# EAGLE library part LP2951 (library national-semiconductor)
Adjustable Micropower Voltage Regulator Source: http://www.national.com/ds/LP/LP2950.pdf
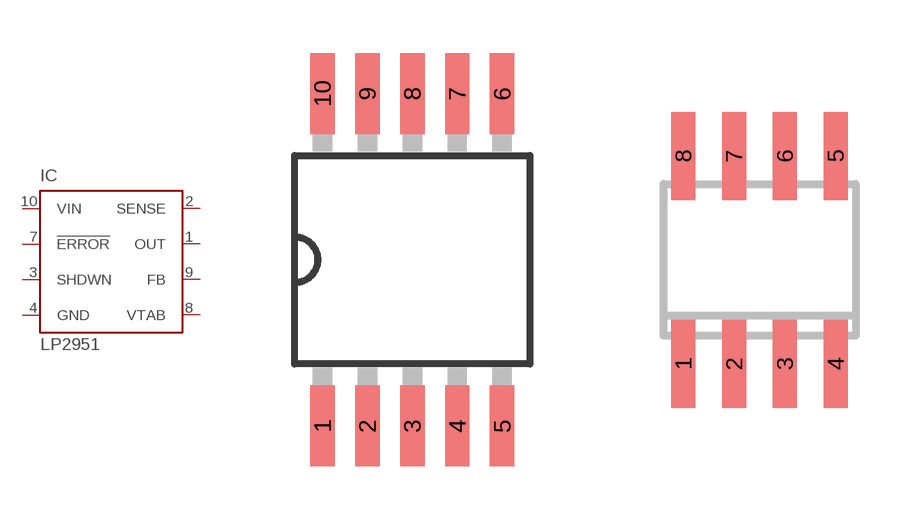
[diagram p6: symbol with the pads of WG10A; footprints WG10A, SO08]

Designator prefix IC

## LP2951WG (OC_FARNELL: unknown; OC_NEWARK: unknown)  [WG10A]
1  OUT  out
2  SENSE  in
3  SHDWN  in
4  GND  pwr
7  !ERROR  out
8  VTAB  in
9  FB  in
10  VIN  in

## LP2951M (MF: FAIRCHILD SEMICONDUCTOR; MPN: LP2951CM; OC_FARNELL: 9488561; OC_NEWARK: 78K6014)  [SO08]
1  OUT  out
2  SENSE  in
3  SHDWN  in
4  GND  pwr
5  !ERROR  out
6  VTAB  in
7  FB  in
8  VIN  in

## LP2951N (MF: ON SEMICONDUCTOR; MPN: LP2951CN; OC_FARNELL: 9489320; OC_NEWARK: 20C0799)  [DIL08]
Pads as for SO08

## LP2951H (OC_FARNELL: unknown; OC_NEWARK: unknown)  [H08C]
Pads as for SO08

## LP2951D (MPN: LP2951D; OC_FARNELL: 1389844; OC_NEWARK: 48M0679)  [LLP8]
Pads as for SO08

## Footprint WG10A (pad centres in mm)
NS Package Number WG10A Source: http://www.national.com/ds/LP/LP2950.pdf
smd 0.69 x 2.29: 1 -2.54,-4.7; 2 -1.27,-4.7; 3 0,-4.7; 4 1.27,-4.7; 5 2.54,-4.7; 6 2.54,4.7; 7 1.27,4.7; 8 0,4.7; 9 -1.27,4.7; 10 -2.54,4.7

## Footprint SO08 (pad centres in mm)
Small Outline Package 8 NS Package M08A
smd 0.6 x 2.2: 1 -1.905,-2.6; 2 -0.635,-2.6; 3 0.635,-2.6; 4 1.905,-2.6; 5 1.905,2.6; 6 0.635,2.6; 7 -0.635,2.6; 8 -1.905,2.6

## Footprint DIL08 (pad centres in mm)
Dual In Line Package
drill 0.813 pad 1.27 round: 1 -3.81,-3.81; 2 -1.27,-3.81; 3 1.27,-3.81; 4 3.81,-3.81; 5 3.81,3.81; 6 1.27,3.81; 7 -1.27,3.81; 8 -3.81,3.81

## Footprint H08C (pad centres in mm)
TO-99 National Semiconductor H08C Motorola MOT 601-04
drill 0.813 octagon: 1 -1.778,-1.778; 2 0,-2.54; 3 1.778,-1.778; 4 2.54,0; 5 1.778,1.778; 6 0,2.54; 7 -1.778,1.778; 8 -2.54,0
